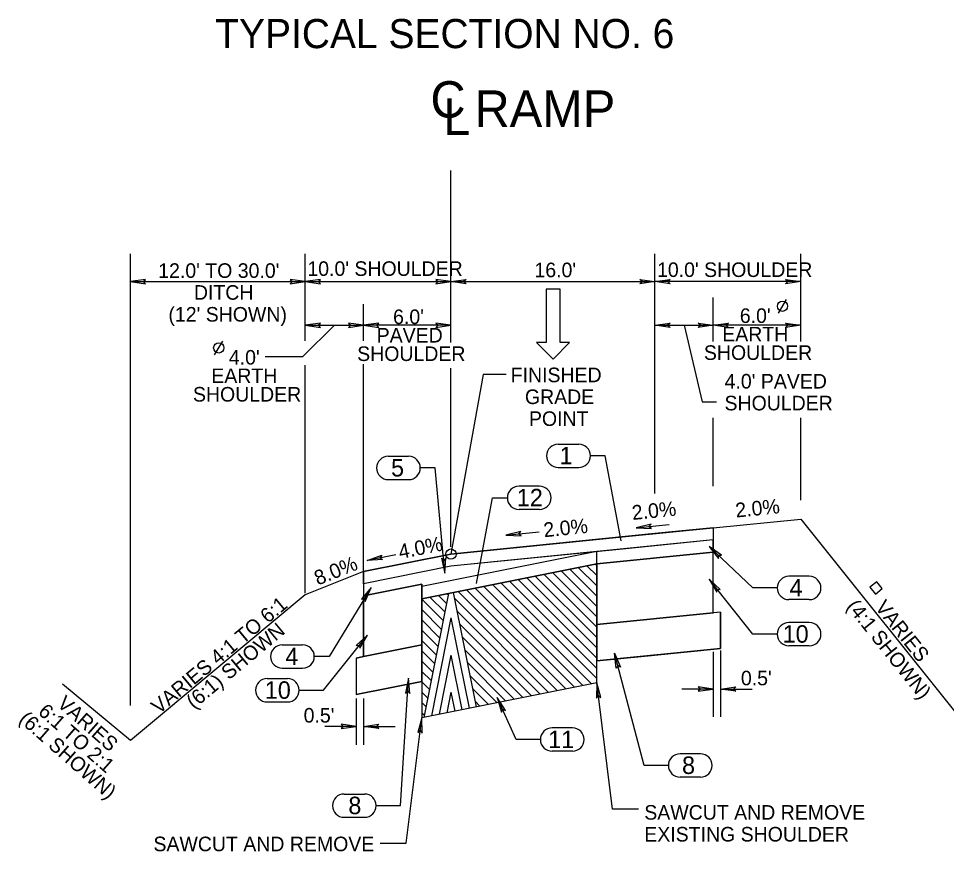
# Model space of a CAD drawing. Extents: x 2003207 to 2014043, y 843846 to 860154.
# Drawn here: x 2013668.4 to 2013732, y 844357.8 to 844414.9 of the extents above; entities that cross this region are included whole.
import ezdxf

# ---------------------------------------------------------------- set-up
doc = ezdxf.new("R2010")
doc.units = 0
for name, color, linetype in [('RD_EX_Pavement_Markings', 7, 'Continuous'), ('RD_EX_Road', 7, 'Continuous'), ('RD_EX_Road_txCode', 7, 'Continuous'), ('RD_QTY_Base_Course', 7, 'Continuous'), ('RD_QTY_ConcPave', 7, 'Continuous'), ('RD_QTY_Intermediate', 7, 'Continuous'), ('RD_QTY_Milling', 7, 'Continuous'), ('RD_QTY_PermVeg', 7, 'Continuous'), ('RD_QTY_Surf_Course', 7, 'Continuous'), ('RD_TX_Misc1', 7, 'Continuous'), ('RD_TX_Misc2', 7, 'Continuous'), ('RD_TX_TypSect', 7, 'Continuous')]:
    doc.layers.add(name, color=color, linetype=linetype)

msp = doc.modelspace()

# ---------------------------------------------------------------- linework, layer by layer
at = {"layer": 'RD_EX_Pavement_Markings'}
msp.add_lwpolyline([(2013705.514, 844396.382), (2013704.554, 844396.382), (2013704.554, 844392.714), (2013703.903, 844392.714), (2013705.034, 844391.582), (2013706.165, 844392.714), (2013705.514, 844392.714)], close=True, dxfattribs=at)
at = {"layer": 'RD_EX_Road'}
for p, q in [((2013708.031, 844378.371), (2013696.031, 844375.971)), ((2013708.031, 844369.375), (2013708.031, 844378.371)), ((2013708.202, 844378.348), (2013708.208, 844378.354)), ((2013708.031, 844377.538), (2013696.031, 844375.138)), ((2013705.588, 844377.05), (2013708.031, 844374.607)), ((2013706.177, 844377.167), (2013708.031, 844375.314)), ((2013706.766, 844377.285), (2013708.031, 844376.021)), ((2013707.356, 844377.403), (2013708.031, 844376.728)), ((2013707.945, 844377.521), (2013708.031, 844377.435)), ((2013702.642, 844376.46), (2013708.031, 844371.071)), ((2013703.231, 844376.578), (2013708.031, 844371.778)), ((2013703.82, 844376.696), (2013708.031, 844372.485)), ((2013704.409, 844376.814), (2013708.031, 844373.192)), ((2013704.999, 844376.932), (2013708.031, 844373.9)), ((2013696.031, 844375.971), (2013696.031, 844366.975)), ((2013699.695, 844375.871), (2013706.498, 844369.069)), ((2013700.285, 844375.989), (2013707.087, 844369.186)), ((2013700.874, 844376.107), (2013707.676, 844369.304)), ((2013701.463, 844376.225), (2013708.031, 844369.657)), ((2013702.052, 844376.342), (2013708.031, 844370.364)), ((2013697.857, 844375.503), (2013696.157, 844367)), ((2013696.588, 844375.25), (2013697.603, 844374.234)), ((2013697.177, 844375.367), (2013697.721, 844374.823)), ((2013697.766, 844375.485), (2013697.839, 844375.413)), ((2013698.191, 844375.57), (2013699.761, 844367.721)), ((2013698.27, 844375.175), (2013704.73, 844368.715)), ((2013698.517, 844375.635), (2013705.319, 844368.833)), ((2013699.106, 844375.753), (2013705.909, 844368.951)), ((2013696.031, 844375.1), (2013697.486, 844373.645)), ((2013696.031, 844374.392), (2013697.368, 844373.056)), ((2013698.447, 844374.291), (2013704.141, 844368.597)), ((2013696.031, 844373.685), (2013697.25, 844372.466)), ((2013698.031, 844373.822), (2013696.688, 844367.107)), ((2013698.031, 844373.822), (2013699.271, 844367.623)), ((2013698.624, 844373.407), (2013703.552, 844368.479)), ((2013696.031, 844372.978), (2013697.132, 844371.877)), ((2013696.031, 844372.271), (2013697.014, 844371.288)), ((2013698.8, 844372.523), (2013702.962, 844368.361)), ((2013696.031, 844371.564), (2013696.896, 844370.698)), ((2013698.977, 844371.639), (2013702.373, 844368.244)), ((2013696.031, 844370.857), (2013696.778, 844370.109)), ((2013698.031, 844371.272), (2013697.219, 844367.213)), ((2013698.031, 844371.272), (2013698.78, 844367.525)), ((2013699.154, 844370.756), (2013701.784, 844368.126)), ((2013696.031, 844370.15), (2013696.661, 844369.52)), ((2013696.031, 844369.443), (2013696.543, 844368.931)), ((2013699.331, 844369.872), (2013701.194, 844368.008)), ((2013708.031, 844369.375), (2013696.031, 844366.975)), ((2013699.507, 844368.988), (2013700.605, 844367.89)), ((2013696.031, 844368.736), (2013696.425, 844368.341)), ((2013698.031, 844368.723), (2013697.75, 844367.319)), ((2013698.031, 844368.723), (2013698.29, 844367.427)), ((2013696.031, 844368.028), (2013696.307, 844367.752)), ((2013699.684, 844368.104), (2013700.016, 844367.772)), ((2013696.031, 844367.321), (2013696.189, 844367.163))]:
    msp.add_line(p, q, dxfattribs=at)
at = {"layer": 'RD_EX_Road_txCode'}
msp.add_lwpolyline([(2013726.784, 844375.933), (2013727.159, 844375.464), (2013727.628, 844375.839), (2013727.253, 844376.307)], close=True, dxfattribs=at)
msp.add_circle((2013698.031, 844378.204), 0.35, dxfattribs=at)
at = {"layer": 'RD_QTY_Base_Course'}
for p, q in [((2013714.031, 844373.971), (2013708.031, 844373.371)), ((2013716.531, 844374.221), (2013714.031, 844373.971)), ((2013716.531, 844374.221), (2013716.031, 844374.171)), ((2013716.531, 844374.221), (2013716.531, 844371.721)), ((2013716.531, 844371.721), (2013716.531, 844374.221)), ((2013708.031, 844373.371), (2013708.031, 844370.871)), ((2013696.031, 844371.971), (2013692.031, 844371.171)), ((2013696.031, 844369.471), (2013696.031, 844371.971)), ((2013716.531, 844371.721), (2013708.031, 844370.871)), ((2013711.991, 844371.267), (2013716.531, 844371.721)), ((2013691.531, 844371.071), (2013692.031, 844371.171)), ((2013692.031, 844371.171), (2013691.531, 844371.071)), ((2013691.531, 844371.071), (2013691.531, 844368.571)), ((2013691.531, 844371.071), (2013691.531, 844368.571)), ((2013708.031, 844370.871), (2013711.8, 844371.248)), ((2013696.031, 844369.471), (2013691.531, 844368.571)), ((2013691.531, 844368.571), (2013696.031, 844369.471))]:
    msp.add_line(p, q, dxfattribs=at)
msp.add_lwpolyline([(2013711.8, 844371.248), (2013711.991, 844371.267)], dxfattribs=at)
at = {"layer": 'RD_QTY_ConcPave'}
for p, q in [((2013716.031, 844378.338), (2013708.031, 844377.538)), ((2013716.031, 844374.171), (2013716.031, 844378.338)), ((2013716.031, 844374.171), (2013716.031, 844378.338)), ((2013708.031, 844377.538), (2013708.031, 844373.371)), ((2013696.031, 844376.138), (2013692.031, 844375.338)), ((2013696.031, 844375.971), (2013696.031, 844376.138)), ((2013696.031, 844375.138), (2013696.031, 844375.971)), ((2013692.031, 844371.171), (2013692.031, 844375.338)), ((2013692.031, 844375.338), (2013692.031, 844371.171)), ((2013696.031, 844371.971), (2013696.031, 844375.138)), ((2013716.031, 844374.171), (2013708.031, 844373.371)), ((2013708.031, 844373.371), (2013716.031, 844374.171)), ((2013696.031, 844371.971), (2013692.031, 844371.171)), ((2013692.031, 844371.171), (2013696.031, 844371.971))]:
    msp.add_line(p, q, dxfattribs=at)
at = {"layer": 'RD_QTY_Intermediate'}
for p, q in [((2013716.031, 844379.171), (2013716.031, 844378.338)), ((2013708.031, 844378.371), (2013698.031, 844377.371)), ((2013716.031, 844378.338), (2013708.031, 844377.538)), ((2013698.031, 844377.371), (2013692.031, 844376.171)), ((2013692.031, 844376.171), (2013692.031, 844375.338)), ((2013692.031, 844376.171), (2013692.031, 844375.338)), ((2013696.031, 844376.138), (2013692.031, 844375.338)), ((2013692.031, 844375.338), (2013696.031, 844376.138)), ((2013696.031, 844376.138), (2013696.031, 844375.971)), ((2013696.031, 844376.138), (2013696.031, 844375.971))]:
    msp.add_line(p, q, dxfattribs=at)
msp.add_lwpolyline([(2013696.031, 844375.971), (2013696.031, 844375.138), (2013708.031, 844377.538), (2013716.031, 844378.338), (2013716.031, 844379.171), (2013708.031, 844378.371)], dxfattribs=at)
at = {"layer": 'RD_QTY_Milling'}
for p, q in [((2013708.031, 844378.371), (2013696.031, 844375.971)), ((2013708.031, 844377.538), (2013708.031, 844378.371)), ((2013696.031, 844375.138), (2013708.031, 844377.538)), ((2013696.031, 844375.971), (2013696.031, 844375.138)), ((2013696.031, 844375.138), (2013696.031, 844375.138)), ((2013696.031, 844375.138), (2013696.031, 844375.138)), ((2013696.031, 844375.138), (2013696.031, 844375.138))]:
    msp.add_line(p, q, dxfattribs=at)
at = {"layer": 'RD_QTY_PermVeg'}
for p, q in [((2013716.031, 844380.004), (2013722.031, 844380.604)), ((2013722.031, 844380.604), (2013734.031, 844365.604)), ((2013692.031, 844377.004), (2013688.031, 844375.404)), ((2013688.031, 844375.404), (2013676.031, 844365.404)), ((2013676.031, 844365.404), (2013671.379, 844369.281))]:
    msp.add_line(p, q, dxfattribs=at)
at = {"layer": 'RD_QTY_Surf_Course'}
for p, q in [((2013712.031, 844379.604), (2013698.031, 844378.204)), ((2013716.031, 844380.004), (2013712.031, 844379.604)), ((2013716.031, 844380.004), (2013716.031, 844379.171)), ((2013698.031, 844378.204), (2013710.031, 844379.404)), ((2013716.031, 844379.171), (2013698.031, 844377.371)), ((2013710.031, 844378.571), (2013698.031, 844377.371)), ((2013698.031, 844378.204), (2013692.031, 844377.004)), ((2013698.031, 844378.204), (2013698.031, 844378.204)), ((2013698.031, 844377.371), (2013692.031, 844376.171)), ((2013698.031, 844377.371), (2013698.031, 844377.371)), ((2013698.031, 844377.371), (2013698.031, 844377.371)), ((2013698.031, 844377.371), (2013698.031, 844377.371)), ((2013692.031, 844377.004), (2013692.031, 844376.171))]:
    msp.add_line(p, q, dxfattribs=at)
for points in [[(2013710.031, 844379.404), (2013716.031, 844380.004), (2013716.031, 844379.171), (2013710.031, 844378.571)], [(2013698.031, 844377.371), (2013692.031, 844376.171), (2013692.031, 844377.004), (2013698.031, 844378.204)]]:
    msp.add_lwpolyline(points, dxfattribs=at)
at = {"layer": 'RD_TX_Misc2'}
for p, q in [((2013705.397, 844385.743), (2013706.797, 844385.743)), ((2013693.727, 844384.911), (2013695.127, 844384.911)), ((2013705.397, 844384.143), (2013706.797, 844384.143)), ((2013693.727, 844383.311), (2013695.127, 844383.311)), ((2013704.1, 844382.862), (2013702.7, 844382.862)), ((2013704.1, 844381.262), (2013702.7, 844381.262)), ((2013722.623, 844376.679), (2013721.223, 844376.679)), ((2013722.623, 844375.079), (2013721.223, 844375.079)), ((2013722.623, 844373.508), (2013721.223, 844373.508)), ((2013686.452, 844371.974), (2013687.852, 844371.974)), ((2013722.623, 844371.908), (2013721.223, 844371.908)), ((2013686.452, 844370.374), (2013687.852, 844370.374)), ((2013685.416, 844369.658), (2013686.816, 844369.658)), ((2013685.416, 844368.058), (2013686.816, 844368.058)), ((2013706.366, 844366.277), (2013704.966, 844366.277)), ((2013706.366, 844364.677), (2013704.966, 844364.677)), ((2013715.153, 844364.501), (2013713.753, 844364.501)), ((2013715.153, 844362.901), (2013713.753, 844362.901)), ((2013690.698, 844361.743), (2013692.098, 844361.743)), ((2013690.698, 844360.143), (2013692.098, 844360.143))]:
    msp.add_line(p, q, dxfattribs=at)
for centre, start, end in [((2013705.397, 844384.943), 90, 270), ((2013706.797, 844384.943), 270, 90), ((2013693.727, 844384.111), 90, 270), ((2013695.127, 844384.111), 270, 90), ((2013702.7, 844382.062), 90, 270), ((2013704.1, 844382.062), 270, 90), ((2013721.223, 844375.879), 90, 270), ((2013722.623, 844375.879), 270, 90), ((2013721.223, 844372.708), 90, 270), ((2013722.623, 844372.708), 270, 90), ((2013686.452, 844371.174), 90, 270), ((2013687.852, 844371.174), 270, 90), ((2013685.416, 844368.858), 90, 270), ((2013686.816, 844368.858), 270, 90), ((2013704.966, 844365.477), 90, 270), ((2013706.366, 844365.477), 270, 90), ((2013713.753, 844363.701), 90, 270), ((2013715.153, 844363.701), 270, 90), ((2013690.698, 844360.943), 90, 270), ((2013692.098, 844360.943), 270, 90)]:
    msp.add_arc(centre, 0.8, start, end, dxfattribs=at)
at = {"layer": 'RD_TX_TypSect'}
for p, q in [((2013698.031, 844392.721), (2013698.031, 844404.526)), ((2013676.031, 844367.819), (2013676.031, 844398.808)), ((2013688.031, 844393.733), (2013688.031, 844398.808)), ((2013712.031, 844382.363), (2013712.031, 844398.808)), ((2013722.031, 844392.794), (2013722.031, 844398.808)), ((2013676.031, 844396.902), (2013688.031, 844396.902)), ((2013688.031, 844396.902), (2013698.031, 844396.902)), ((2013698.031, 844396.902), (2013712.031, 844396.902)), ((2013722.031, 844396.902), (2013712.031, 844396.902)), ((2013716.031, 844392.794), (2013716.031, 844395.808)), ((2013720.497, 844394.734), (2013721.063, 844395.677)), ((2013688.031, 844392.84), (2013688.031, 844395.341)), ((2013692.031, 844392.84), (2013692.031, 844395.354)), ((2013688.031, 844393.902), (2013692.031, 844393.902)), ((2013698.031, 844393.902), (2013692.031, 844393.902)), ((2013712.031, 844393.902), (2013716.031, 844393.902)), ((2013722.031, 844393.902), (2013716.031, 844393.902)), ((2013681.812, 844391.876), (2013682.378, 844392.819)), ((2013688.031, 844375.51), (2013688.031, 844391.164)), ((2013692.031, 844376.273), (2013692.031, 844391.233)), ((2013698.031, 844378.704), (2013698.031, 844390.963)), ((2013716.031, 844382.862), (2013716.031, 844387.547)), ((2013722.031, 844381.905), (2013722.031, 844387.547)), ((2013701.799, 844379.503), (2013704.076, 844379.731)), ((2013710.739, 844379.995), (2013713.016, 844380.223)), ((2013694.237, 844378.162), (2013692.286, 844377.772)), ((2013716.031, 844371.486), (2013716.031, 844367.026)), ((2013716.531, 844371.581), (2013716.531, 844367.026)), ((2013716.031, 844368.937), (2013713.863, 844368.937)), ((2013716.531, 844368.937), (2013718.698, 844368.937)), ((2013691.531, 844368.299), (2013691.531, 844365.107)), ((2013692.031, 844368.299), (2013692.031, 844365.107)), ((2013691.531, 844366.379), (2013689.363, 844366.379)), ((2013692.031, 844366.379), (2013694.198, 844366.379))]:
    msp.add_line(p, q, dxfattribs=at)
for points in [[(2013676.031, 844396.902), (2013677.07, 844396.752), (2013676.91, 844396.902), (2013677.07, 844397.051)], [(2013688.031, 844396.902), (2013686.992, 844397.051), (2013687.152, 844396.902), (2013686.992, 844396.752)], [(2013688.031, 844396.902), (2013689.07, 844396.752), (2013688.91, 844396.902), (2013689.07, 844397.051)], [(2013698.031, 844396.902), (2013696.992, 844397.051), (2013697.152, 844396.902), (2013696.992, 844396.752)], [(2013698.031, 844396.902), (2013699.07, 844397.051), (2013698.91, 844396.902), (2013699.07, 844396.752)], [(2013712.031, 844396.902), (2013710.992, 844396.752), (2013711.152, 844396.902), (2013710.992, 844397.051)], [(2013712.031, 844396.902), (2013713.07, 844397.051), (2013712.91, 844396.902), (2013713.07, 844396.752)], [(2013722.031, 844396.902), (2013720.992, 844396.752), (2013721.152, 844396.902), (2013720.992, 844397.051)], [(2013688.031, 844393.902), (2013689.07, 844393.752), (2013688.91, 844393.902), (2013689.07, 844394.051)], [(2013692.031, 844393.902), (2013690.992, 844394.051), (2013691.152, 844393.902), (2013690.992, 844393.752)], [(2013692.031, 844393.902), (2013693.07, 844393.752), (2013692.91, 844393.902), (2013693.07, 844394.051)], [(2013698.031, 844393.902), (2013696.992, 844394.051), (2013697.152, 844393.902), (2013696.992, 844393.752)], [(2013712.031, 844393.902), (2013713.07, 844394.051), (2013712.91, 844393.902), (2013713.07, 844393.752)], [(2013716.031, 844393.902), (2013714.992, 844393.752), (2013715.152, 844393.902), (2013714.992, 844394.051)], [(2013716.031, 844393.902), (2013717.07, 844394.051), (2013716.91, 844393.902), (2013717.07, 844393.752)], [(2013722.031, 844393.902), (2013720.992, 844393.752), (2013721.152, 844393.902), (2013720.992, 844394.051)], [(2013710.739, 844379.995), (2013711.788, 844379.949), (2013711.614, 844380.083), (2013711.758, 844380.248)], [(2013701.799, 844379.503), (2013702.847, 844379.457), (2013702.673, 844379.591), (2013702.818, 844379.756)], [(2013715.743, 844378.728), (2013716.395, 844377.905), (2013716.382, 844378.124), (2013716.601, 844378.123)], [(2013692.286, 844377.772), (2013693.275, 844378.123), (2013693.148, 844377.944), (2013693.334, 844377.829)], [(2013697.62, 844376.898), (2013697.672, 844377.946), (2013697.537, 844377.772), (2013697.373, 844377.917)], [(2013715.743, 844376.493), (2013716.273, 844375.587), (2013716.29, 844375.806), (2013716.507, 844375.774)], [(2013692.547, 844375.918), (2013691.88, 844375.109), (2013692.091, 844375.167), (2013692.136, 844374.953)], [(2013692.296, 844372.644), (2013691.531, 844371.925), (2013691.748, 844371.956), (2013691.766, 844371.738)], [(2013709.258, 844371.416), (2013709.667, 844370.45), (2013709.481, 844370.566), (2013709.377, 844370.374)], [(2013695.116, 844369.679), (2013694.901, 844368.652), (2013695.061, 844368.802), (2013695.2, 844368.633)], [(2013708.031, 844369.375), (2013708.012, 844368.326), (2013708.141, 844368.503), (2013708.31, 844368.363)], [(2013716.031, 844368.937), (2013714.992, 844369.087), (2013715.152, 844368.937), (2013714.992, 844368.787)], [(2013716.531, 844368.937), (2013717.57, 844369.087), (2013717.41, 844368.937), (2013717.57, 844368.787)], [(2013701.203, 844368.37), (2013701.489, 844367.36), (2013701.56, 844367.567), (2013701.763, 844367.482)], [(2013696.031, 844366.975), (2013695.753, 844365.963), (2013695.921, 844366.103), (2013696.05, 844365.926)], [(2013691.531, 844366.379), (2013690.492, 844366.529), (2013690.652, 844366.379), (2013690.492, 844366.229)], [(2013692.031, 844366.379), (2013693.07, 844366.529), (2013692.91, 844366.379), (2013693.07, 844366.229)]]:
    msp.add_lwpolyline(points, close=True, dxfattribs=at)
for points in [[(2013685.29, 844391.753), (2013687.873, 844391.753), (2013690.031, 844393.897)], [(2013714.031, 844393.902), (2013715.271, 844388.655), (2013716.259, 844388.655)], [(2013701.818, 844390.527), (2013700.248, 844390.527), (2013698.031, 844378.204)], [(2013709.711, 844379.119), (2013708.606, 844384.943), (2013707.597, 844384.943)], [(2013697.62, 844376.898), (2013696.936, 844384.111), (2013695.927, 844384.111)], [(2013699.774, 844376.176), (2013700.891, 844382.062), (2013701.9, 844382.062)], [(2013720.423, 844375.879), (2013718.757, 844375.879), (2013715.743, 844378.728)], [(2013720.423, 844372.708), (2013718.757, 844372.708), (2013715.743, 844376.493)], [(2013692.547, 844375.918), (2013689.661, 844371.174), (2013688.652, 844371.174)], [(2013687.616, 844368.858), (2013689.282, 844368.858), (2013692.296, 844372.644)], [(2013712.953, 844363.701), (2013711.288, 844363.701), (2013709.258, 844371.416)], [(2013692.898, 844360.943), (2013694.563, 844360.943), (2013695.116, 844369.679)], [(2013710.9, 844360.706), (2013709.125, 844360.706), (2013708.031, 844369.375)], [(2013704.166, 844365.477), (2013702.501, 844365.477), (2013701.203, 844368.37)], [(2013693.178, 844358.38), (2013694.953, 844358.38), (2013696.031, 844366.975)]]:
    msp.add_lwpolyline(points, dxfattribs=at)
for centre in [(2013720.78, 844395.206), (2013682.095, 844392.347)]:
    msp.add_circle(centre, 0.35, dxfattribs=at)

# ---------------------------------------------------------------- texts
at = {"layer": 'RD_TX_Misc1'}
for s, p in [('C', (2013696.622, 844408.143)), ('RAMP', (2013699.648, 844407.514)), ('L', (2013697.5, 844406.962))]:
    msp.add_text(s, height=2.5, dxfattribs=at).set_placement(p)
at = {"layer": 'RD_TX_Misc2'}
for s, p in [('1', (2013705.485, 844384.359)), ('5', (2013693.918, 844383.526)), ('12', (2013702.551, 844381.477)), ('4', (2013721.268, 844375.294)), ('10', (2013720.792, 844372.123)), ('4', (2013686.665, 844370.589)), ('10', (2013685.254, 844368.274)), ('11', (2013704.705, 844364.893)), ('8', (2013713.889, 844363.117)), ('8', (2013690.989, 844360.358))]:
    msp.add_text(s, height=1.2, dxfattribs=at).set_placement(p)
at = {"layer": 'RD_TX_TypSect'}
for s, height, p in [('TYPICAL SECTION NO. 6', 2, (2013681.851, 844412.912)), ("12.0' TO 30.0'", 1, (2013677.94, 844397.152)), ("10.0' SHOULDER", 1, (2013688.176, 844397.287)), ("16.0'", 1, (2013703.759, 844397.197)), ("10.0' SHOULDER", 1, (2013712.172, 844397.213)), ('DITCH', 1, (2013680.389, 844395.652)), ("(12' SHOWN)", 1, (2013678.641, 844394.152)), ("6.0'", 1, (2013694.058, 844393.983)), ("6.0'", 1, (2013717.853, 844394.059)), ('PAVED', 1, (2013692.932, 844392.716)), ('EARTH', 1, (2013716.648, 844392.791)), ('SHOULDER', 1, (2013691.594, 844391.448)), ('SHOULDER', 1, (2013715.388, 844391.524)), ("4.0'", 1, (2013682.789, 844391.201)), ('EARTH', 1, (2013681.584, 844389.933)), ('FINISHED', 1, (2013702.129, 844389.994)), ("4.0' PAVED", 1, (2013716.81, 844389.562)), ('SHOULDER', 1, (2013680.324, 844388.665)), ('GRADE', 1, (2013703.106, 844388.494)), ('SHOULDER', 1, (2013716.803, 844388.062)), ('POINT', 1, (2013703.381, 844386.994)), ("0.5'", 1, (2013717.929, 844369.201)), ("0.5'", 1, (2013687.92, 844366.643)), ('SAWCUT AND REMOVE', 1, (2013711.298, 844359.983)), ('EXISTING SHOULDER', 1, (2013711.298, 844358.483)), ('SAWCUT AND REMOVE', 1, (2013677.614, 844357.817))]:
    msp.add_text(s, height=height, dxfattribs=at).set_placement(p)
for s, rotation, p in [('2.0%', 5.71059, (2013710.496, 844380.541)), ('2.0%', 5.71059, (2013717.6, 844380.706)), ('2.0%', 5.71059, (2013704.432, 844379.356)), ('4.0%', 11.30993, (2013694.538, 844377.857)), ('8.0%', 21.80141, (2013688.891, 844376.04)), ('VARIES 4:1 TO 6:1', 39.80557, (2013677.986, 844367.176)), ('VARIES', 308.65981, (2013727.087, 844374.534)), ('(4:1 SHOWN)', 308.65981, (2013725.124, 844374.587)), (' (6:1) SHOWN', 39.80557, (2013680.104, 844367.291)), ('VARIES ', 318.68898, (2013670.937, 844367.828)), ('6:1 TO 2:1', 318.68898, (2013669.633, 844367.287)), ('(6:1 SHOWN)', 318.68898, (2013668.311, 844366.761))]:
    msp.add_text(s, height=1, rotation=rotation, dxfattribs=at).set_placement(p)

doc.saveas('drawing.dxf')
